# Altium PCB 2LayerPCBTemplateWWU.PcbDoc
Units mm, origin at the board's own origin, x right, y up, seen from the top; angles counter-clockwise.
Board outline 24.34 x 30.25 mm, 2 copper layers (Top Layer, Bottom Layer); 9 components, 9 nets, 39 pads, 16 vias.
Unrouted connection lines stored in the file: 1.
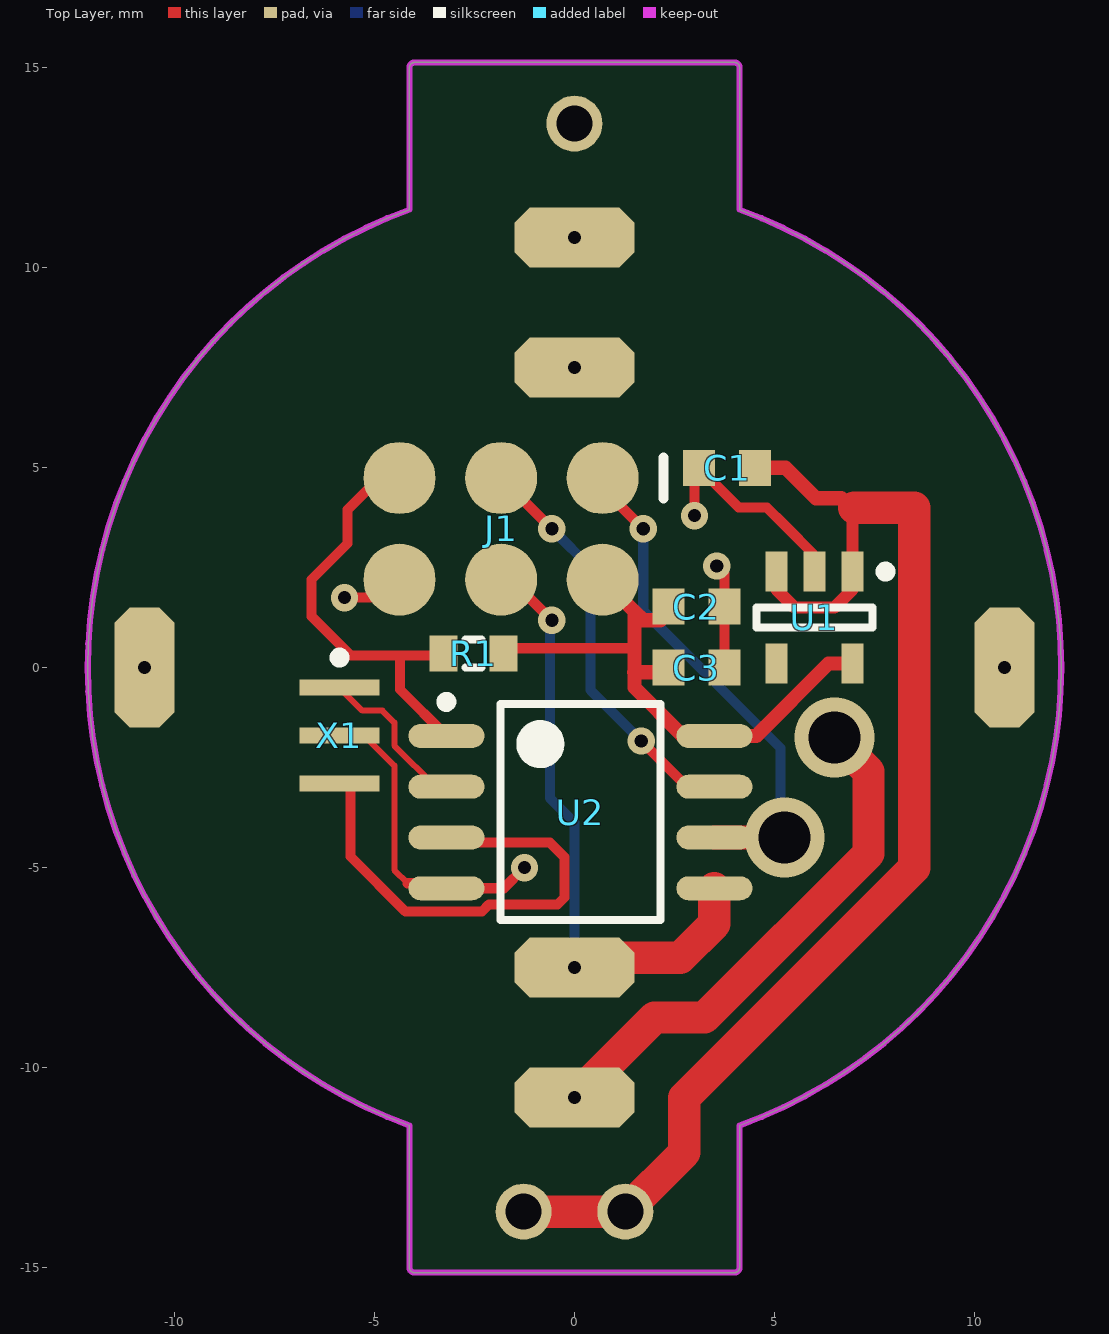
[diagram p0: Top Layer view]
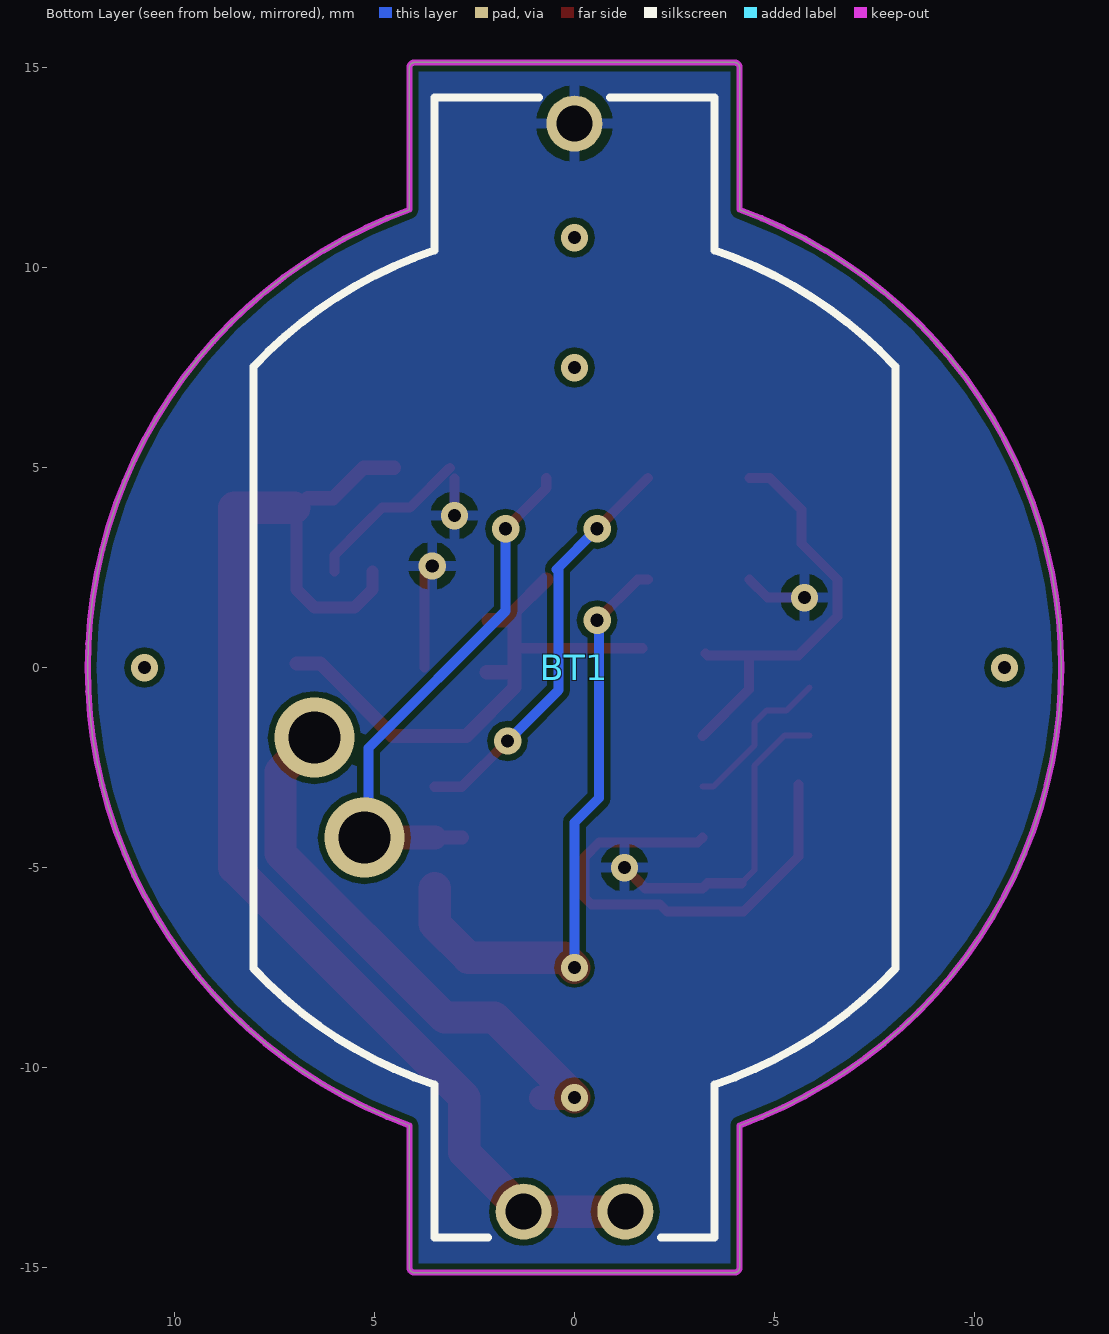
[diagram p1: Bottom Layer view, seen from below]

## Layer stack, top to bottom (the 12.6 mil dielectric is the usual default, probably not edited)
Top Solder: solder mask 0.0102, Solder Resist, Dk 3.5
Top Layer: signal copper 0.0356
Dielectric 1: dielectric 0.32, FR-4, Dk 4.8
Bottom Layer: signal copper 0.0356
Bottom Solder: solder mask 0.0102, Solder Resist, Dk 3.5

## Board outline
-4.127,-11.448 cw(c0,0) -12.169,0 cw(c0,0) -4.127,11.448 -4.127,15 cw(c-4,15) -4,15.127 4,15.127 cw(c4,15) 4.127,15 4.127,11.448 cw(c0,0) 12.169,0 cw(c0,0) 4.127,-11.448 4.127,-15 cw(c4,-15) 4,-15.127 -4,-15.127 cw(c-4,-15) -4.127,-15

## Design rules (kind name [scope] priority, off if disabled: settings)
Clearance [All] p1: gap=0.152
HoleSize [All] p1: absolutevalues=TRUE maxlimit=3.175 minlimit=0.33 maxpercent=80.000 minpercent=20.000
MinimumSolderMaskSliver [All] p1: minsoldermaskwidth=0.025
PolygonConnect [All] p1: connectstyle=Relief reliefconductorwidth=0.254 reliefentries=4 polygonreliefangle="90 Angle" airgapwidth=0.254
RoutingVias [All] p1: holewidth=0.33 width=0.508 viastyle="Through Hole" minholewidth=0.33 minwidth=0.508 maxholewidth=3.175 maxwidth=6.35
SilkToSilkClearance [All] p1: silktosilkclearance=0.102
SilkToSolderMaskClearance [IsPad] p1: minsilkscreentomaskgap=0.152 clearancetoexposedcopper=TRUE
SolderMaskExpansion [All] p1: expansion=0.102
UnpouredPolygon [All] p1: allowunpoured=FALSE
Width [All] p1: maxlimit=12.7 minlimit=0.152 preferedwidth=0.635
25 further rules are at their usual default settings.

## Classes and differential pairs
component class BSheetSchematicTemplateWWU: C1 C2 C3 J1 R1 U1 U2 X1

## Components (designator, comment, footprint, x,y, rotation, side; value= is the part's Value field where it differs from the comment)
BT1 "HU2032-LF" RENA-HU2032-LF_V 0,0 r90 bottom
C1 "Cap Semi" 1608[0603] 3.815,4.993 r0 top
C2 "Cap Semi" 1608[0603] 3.048,1.524 r180 top
C3 "Cap Semi" 1608[0603] 3.048,0 r180 top
J1 "AVR ISP" AVR_ISP 0.705,4.739 r270 top
R1 "Res3" J1-0603 -2.525,0.35 r0 top
U1 "NCP500SN33T1GOSCT" ONSC-SOT23-5_L 6,1.25 r270 top
U2 "ATtiny85V-10SH" 8S2_L 0.147,-3.613 r0 top
X1 "CSTCE8M00G55-R0" MURA-CSTCE_G_A-3_V -5.875,-1.7 r270 top

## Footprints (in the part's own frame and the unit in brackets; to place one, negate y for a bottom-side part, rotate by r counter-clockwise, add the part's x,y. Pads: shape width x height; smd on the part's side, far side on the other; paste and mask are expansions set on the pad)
8S2_L [mm] "SOP, 8-Leads, Body 5.3x5.3mm, Pitch 1.27mm, IPC High Density"
  oval 1.9x0.6 smd: 1(-3.35,1.905) 2(-3.35,0.635) 3(-3.35,-0.635) 4(-3.35,-1.905) 5(3.35,-1.905) 6(3.35,-0.635) 7(3.35,0.635) 8(3.35,1.905)
  silkscreen extent -3.47,-2.7 2,2.88, body extent -2.7,-2.68 2.7,2.68, height 2.16
1608[0603] [mm] "Chip Capacitor, Body 1.6x0.8mm, IPC High Density"
  rect 0.8x0.9 smd: 1(-0.7,0) 2(0.7,0)
  body extent -0.87,-0.48 0.87,0.48, height 1.3
AVR_ISP [mm] "AVR_ISP POGO CONNECTOR"
  round 1.8 smd: 1(0,0) 2(2.54,0) 3(0,-2.54) 4(2.54,-2.54) 5(0,-5.08) 6(2.54,-5.08)
  silkscreen extent -0.51,1.52 0.51,1.52
J1-0603 [mm] "Chip Resistor, Body 1.6x0.8mm, IPC High Density"
  rect 0.7x0.9 smd: 1(-0.75,0) 2(0.75,0)
  silkscreen extent -0.2,-0.35 0.2,0.35, body extent -0.85,-0.48 0.85,0.48, height 0.9
MURA-CSTCE_G_A-3_V [mm] "SMD, 3-Leads, Body 3.2x1.3mm, Pitch 1.2mm"
  rect 0.4x2 smd: 1(-1.2,0) 2(0,0) 3(1.2,0)
  silkscreen extent -2.07,-0.12 -1.83,0.13, body extent -1.6,-0.65 1.6,0.65, height 0.7
ONSC-SOT23-5_L [mm] "SOT23, 5-Leads, Body 2.90x1.6mm, Pitch 0.95mm, IPC High Density"
  rect 1x0.55 smd: 1(-1.15,0.95) 2(-1.15,0) 3(-1.15,-0.95) 4(1.15,-0.95) 5(1.15,0.95)
  silkscreen extent -1.27,-1.45 0.25,1.9, body extent -0.8,-1.45 0.8,1.45, height 1
RENA-HU2032-LF_V [mm] "THD, 3-Leads, Body 28.5x16.05mm"
  round 1.4 hole 0.9: 1(-13.6,1.27) 2(-13.6,-1.27) 3(13.6,0)
  silkscreen extent -14.25,-8.03 14.25,8.03, body extent -14.25,-8.03 14.25,8.03, height 5.35

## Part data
BT1: library part CMP-2000-06429-1, "Coin Cell Battery Holder, CR2032, Horizontal, -40 to 100 degC, 3-Pin THD, RoHS, Tray"
C1 C2 C3: "Capacitor (Semiconductor SIM Model)"
J1: library part AVR_ISP, "AVR ISP POGO CONNECTOR"
R1: "Resistor"
U1: library part CMP-0273-00001-2, "Fixed Low Drop Positive Voltage Regulator, 3.3V, 5-Pin TSOT-23, Tape and Reel"
U2: library part CMP-0093-00338-1, "8-bit AVR Microcontroller, 10MHz, 1.8-5.5V, 8K Flash, 512 Bytes EEPROM, 512 Bytes SRAM, Industrial Grade (-40°C to 85°C), 8-Lead SOIC, Pb-Free"
X1: library part CMP-2100-03620-1, "Ceramic Resonator, 8 MHz, +/- 0.5%, -20 to 80 degC, 3-Pin SMD, RoHS, Tape and Reel"

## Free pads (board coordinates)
  oct 1.5x3 smd: 0(-10.75,0) 0(10.75,0)
  oct 3x1.5 smd: 0(0,-10.75) 0(0,-7.5) 0(0,7.5) 0(0,10.75)

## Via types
v1: diameter 0.686, hole 0.33, Top Layer to Bottom Layer, tented both sides, 14 vias
v2: diameter 2, hole 1.3, Top Layer to Bottom Layer, 2 vias

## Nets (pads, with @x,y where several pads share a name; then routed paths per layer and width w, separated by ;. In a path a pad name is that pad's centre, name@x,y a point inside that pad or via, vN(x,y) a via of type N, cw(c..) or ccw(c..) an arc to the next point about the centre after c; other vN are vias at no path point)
GND: BT1.3 C1.1 C2.1 C3.1 J1.6 U1.2 U2.4 X1.2 | length 17.3
  Top Layer w0.152: X1.2 -5.25,-1.7 -4.5,-2.45 -4.5,-5.062 -4.171,-5.391
  Top Layer w0.254: v1(-5.75,1.75) -4.824,1.75 J1.6 ; -4.171,-5.391 -3.33,-5.391 U2.4 -1.768,-5.518 v1(-1.25,-5) ; v1(3,3.8) C1.1@3,4.73 ; C1.1 4.108,4 4.808,4 5.241,3.567 6,2.808 U1.2 ; v1(3.556,2.54) 3.748,2.348 C2.1 C3.1
MISO: J1.1 pad.0@0,-10.75 U2.6 | length 26
  Top Layer w0.254: J1.1 0.705,4.485 v1(1.721,3.469) ; v2@4.498,-4.248 v2@4.627,-4.248
  Top Layer w0.356: U2.6@2.814,-4.248 U2.6
  Top Layer w0.61: v1(0,-10.75) pad.0@0.833,-10.75 ; U2.6 v2@4.498,-4.248
  Top Layer w0.8: v1(0,-10.75) 2,-8.75 3.25,-8.75 7.348,-4.652 7.348,-2.598 v2(6.5,-1.75)
  Bottom Layer w0.254: v1(1.721,3.469) 1.721,1.417 5.15,-2.012 v2@5.15,-3.675
  other v2: 5.25,-4.25
MOSI: J1.4 pad.0@0,-7.5 U2.5 | length 15.8
  Top Layer w0.254: J1.4 -1.581,2.199 v1(-0.565,1.183) ; v1(0,-7.5) pad.0@0,-7.161
  Top Layer w0.813: v1(0,-7.5) 0.25,-7.25 2.65,-7.25 3.497,-6.403 U2.5
  Bottom Layer w0.254: v1@-0.615,1.183 -0.615,-3.26 0,-3.875 v1(0,-7.5)
RST: J1.5 R1.1 U2.1 | length 10.9
  Top Layer w0.254: J1.5 -4.883,4.739 -5.675,3.947 -5.675,3.1 -6.575,2.2 -6.575,1.28 -5.595,0.3 -4.361,0.3 ; R1.1 -3.325,0.3 -4.361,0.3 ; U2.1 -4.361,-0.55 -4.361,0.3
SCK: J1.3 U2.7 | length 10.3
  Top Layer w0.254: J1.3 v1(-0.565,3.469) ; v1(1.671,-1.835) 2.814,-2.978 U2.7
  Bottom Layer w0.254: v1(-0.565,3.469) 0.451,2.453 ; 0.401,2.45 0.401,-0.565 v1(1.671,-1.835)
VCC: C2.2 C3.2 J1.2 R1.2 U1.5 U2.8 | length 14.4
  Top Layer w0.254: R1.2@-1.7,0.484 1.5,0.484 1.53,0.484
  Top Layer w0.356: J1.2 J1.2 1.5,1.402 ; 1.497,-0.119 1.5,-0.122 1.5,-0.5 2.708,-1.708 U2.8 4.542,-1.708 6.35,0.1 U1.5 ; C2.2@2.147,1.181 1.721,1.181 1.5,1.402 ; C3.2@2.197,-0.119 1.503,-0.119 1.5,-0.116 1.5,0.484 1.5,1.402
VIN: BT1.1 BT1.2 C1.2 U1.1 U1.3 | length 32.3
  Top Layer w0.305: U1.3 5.05,1.95 5.5,1.5 6.5,1.5 6.95,1.95 U1.1 6.95,3.95 7,4
  Top Layer w0.356: C1.2 5.277,4.993 6.039,4.231 6.669,4.231 6.95,3.95
  Top Layer w0.813: BT1.2 BT1.1 2.75,-12.12 2.75,-10.75 8.5,-5 8.5,4 7,4
XTAL1: U2.2 X1.1 | length 4
  Top Layer w0.152: X1.1 -5.3,-1.075 -4.8,-1.075 -4.5,-1.375 -4.5,-1.95 -3.472,-2.978 U2.2
XTAL2: U2.3 X1.3 | length 12
  Top Layer w0.254: X1.3@-5.6,-2.925 -5.6,-4.724 -4.227,-6.097 -2.313,-6.097 -2.14,-5.924 -0.424,-5.924 -0.25,-5.75 -0.25,-4.74 -0.615,-4.375 -3.076,-4.375 U2.3
pads on no net: U1.4
copper on no net:
  other v1: -10.75,0 10.75,0 0,7.5 0,10.75

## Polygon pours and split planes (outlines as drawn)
GND on Bottom Layer "GND_BTTM" (solid, pour order 4): -4.127,-11.448 cw(c0,0) -12.169,0 cw(c0,0) -4.127,11.448 -4.127,15 cw(c-4,15) -4,15.127 4,15.127 cw(c4,15) 4.127,15 4.127,11.448 cw(c0,0) 12.169,0 cw(c0,0) 4.127,-11.448 4.127,-15 cw(c4,-15) 4,-15.127 -4,-15.127 cw(c-4,-15) -4.127,-15

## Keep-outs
Keep-Out Layer:
  the board outline again, w0.152

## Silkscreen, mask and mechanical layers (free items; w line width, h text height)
Mechanical 19:
  circle w0.254: c0,0 r9.997
  circle w0.254: c0,0 r8.25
